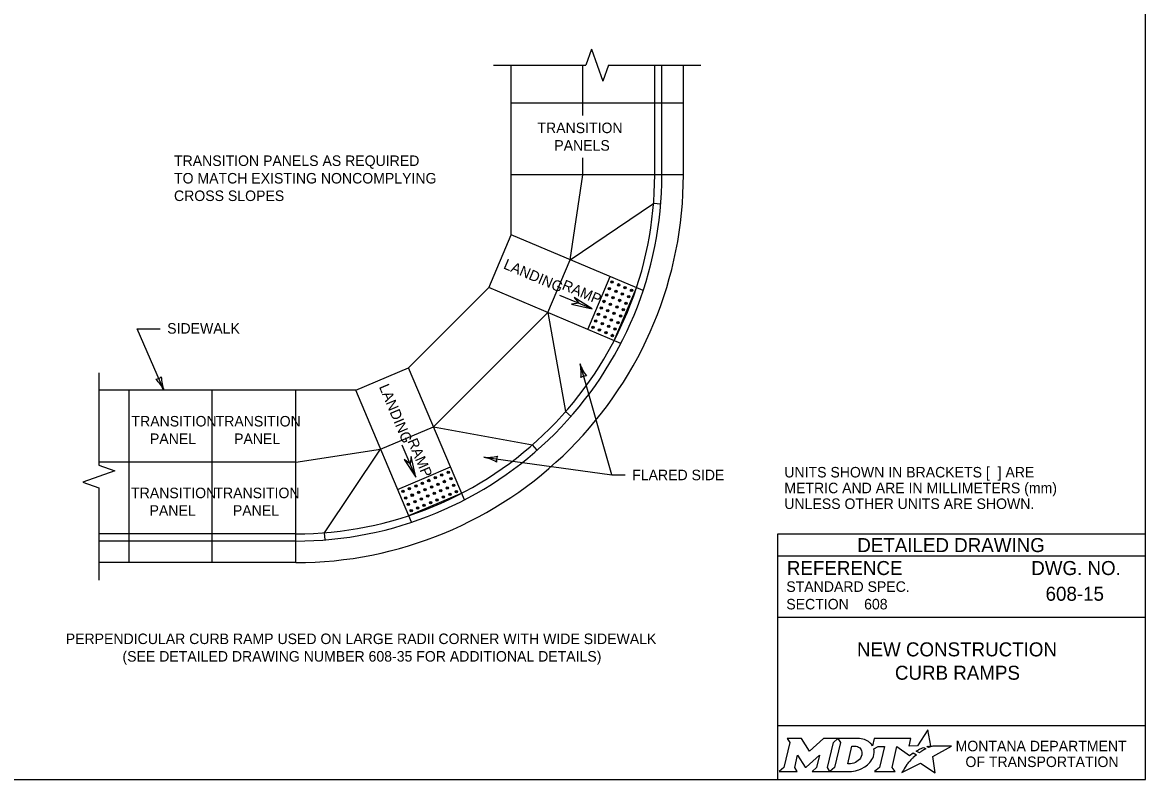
# Model space of a CAD drawing. Extents: x 49991.4 to 50021, y 49987.6 to 50011.4.
# Drawn here: x 50014.53 to 50020.94, y 49999.89 to 50004.2 of the extents above; entities that cross this region are included whole.
import ezdxf

# ---------------------------------------------------------------- set-up
doc = ezdxf.new("R2010")
doc.units = 0
for name, color, linetype in [('Default', 7, 'Continuous'), ('Level 1', 7, 'Continuous'), ('Level 2', 7, 'Continuous'), ('Level 3', 7, 'Continuous'), ('Level 4', 7, 'Continuous'), ('Level 6', 7, 'Continuous')]:
    doc.layers.add(name, color=color, linetype=linetype)

msp = doc.modelspace()

# ---------------------------------------------------------------- linework, layer by layer
at = {"layer": 'Default'}
for points in [[(50019.7003, 50000.0679), (50019.69, 50000.0735), (50019.7016, 50000.0763), (50019.7132, 50000.0783), (50019.6958, 50000.1684), (50019.6363, 50000.0771), (50019.589, 50000.0764), (50019.5993, 50000.1205), (50019.3901, 50000.1206), (50019.38, 50000.0781), (50019.3742, 50000.0864)], [(50019.7003, 50000.0679), (50019.69, 50000.0735), (50019.7016, 50000.0763), (50019.7132, 50000.0783), (50019.6958, 50000.1684), (50019.6363, 50000.0771), (50019.589, 50000.0764), (50019.5993, 50000.1205), (50019.3901, 50000.1206), (50019.38, 50000.0781), (50019.3742, 50000.0864)], [(50018.8933, 50000.1206), (50018.9074, 50000.0972), (50018.8739, 49999.9539), (50018.8482, 49999.9314), (50018.9498, 49999.9314), (50018.9363, 49999.9542), (50018.9525, 50000.0243), (50018.9962, 49999.9553), (50019.0015, 49999.9553), (50019.0766, 50000.0248), (50019.0602, 49999.9537), (50019.0355, 49999.9317), (50019.1371, 49999.9317), (50019.1233, 49999.955), (50019.1565, 50000.0974)], [(50018.8933, 50000.1206), (50018.9074, 50000.0972), (50018.8739, 49999.9539), (50018.8482, 49999.9314), (50018.9498, 49999.9314), (50018.9363, 49999.9542), (50018.9525, 50000.0243), (50018.9962, 49999.9553), (50019.0015, 49999.9553), (50019.0766, 50000.0248), (50019.0602, 49999.9537), (50019.0355, 49999.9317), (50019.1371, 49999.9317), (50019.1233, 49999.955), (50019.1565, 50000.0974)], [(50019.1565, 50000.0974), (50019.1818, 50000.1206), (50019.0994, 50000.1206), (50019.0198, 50000.0476), (50018.9753, 50000.1203), (50018.8933, 50000.1206)], [(50019.1565, 50000.0974), (50019.1818, 50000.1206), (50019.0994, 50000.1206), (50019.0198, 50000.0476), (50018.9753, 50000.1203), (50018.8933, 50000.1206)], [(50019.2954, 50000.1206), (50019.1818, 50000.1206), (50019.1965, 50000.0977), (50019.1626, 49999.9539), (50019.1371, 49999.9317), (50019.2477, 49999.9317)], [(50019.2954, 50000.1206), (50019.1818, 50000.1206), (50019.1965, 50000.0977), (50019.1626, 49999.9539), (50019.1371, 49999.9317), (50019.2477, 49999.9317)], [(50019.3194, 50000.0339), (50019.3182, 50000.0258), (50019.315, 50000.0165), (50019.3108, 50000.0083), (50019.3052, 50000.0008), (50019.2987, 49999.9939), (50019.2908, 49999.9876), (50019.2825, 49999.9829), (50019.2734, 49999.979), (50019.2643, 49999.9767), (50019.2551, 49999.9758), (50019.2392, 49999.9758), (50019.2628, 50000.0758), (50019.2788, 50000.0758), (50019.2864, 50000.0752), (50019.294, 50000.0733), (50019.3006, 50000.0703), (50019.3067, 50000.0661), (50019.3115, 50000.0611), (50019.3152, 50000.0551), (50019.3179, 50000.0489), (50019.3195, 50000.0415), (50019.3195, 50000.0385), (50019.3194, 50000.0339)], [(50019.3194, 50000.0339), (50019.3182, 50000.0258), (50019.315, 50000.0165), (50019.3108, 50000.0083), (50019.3052, 50000.0008), (50019.2987, 49999.9939), (50019.2908, 49999.9876), (50019.2825, 49999.9829), (50019.2734, 49999.979), (50019.2643, 49999.9767), (50019.2551, 49999.9758), (50019.2392, 49999.9758), (50019.2628, 50000.0758), (50019.2788, 50000.0758), (50019.2864, 50000.0752), (50019.294, 50000.0733), (50019.3006, 50000.0703), (50019.3067, 50000.0661), (50019.3115, 50000.0611), (50019.3152, 50000.0551), (50019.3179, 50000.0489), (50019.3195, 50000.0415), (50019.3195, 50000.0385), (50019.3194, 50000.0339)], [(50019.3868, 50000.0615), (50019.4114, 50000.0746), (50019.4483, 50000.0746), (50019.4197, 49999.9541), (50019.3922, 49999.9314), (50019.5084, 49999.9314), (50019.4914, 49999.9543), (50019.5196, 50000.0745), (50019.5909, 50000.0228), (50019.612, 50000.0379), (50019.6317, 50000.027)], [(50019.3868, 50000.0615), (50019.4114, 50000.0746), (50019.4483, 50000.0746), (50019.4197, 49999.9541), (50019.3922, 49999.9314), (50019.5084, 49999.9314), (50019.4914, 49999.9543), (50019.5196, 50000.0745), (50019.5909, 50000.0228), (50019.612, 50000.0379), (50019.6317, 50000.027)], [(50019.5759, 49999.9711), (50019.5606, 49999.9467), (50019.5559, 49999.9392), (50019.5501, 49999.9306), (50019.5478, 49999.9263), (50019.6531, 49999.9794), (50019.737, 49999.9243), (50019.7239, 50000.017), (50019.8308, 50000.0754), (50019.7815, 50000.0762), (50019.7514, 50000.0766), (50019.7306, 50000.0769), (50019.7238, 50000.0754), (50019.7189, 50000.0742), (50019.7105, 50000.0719), (50019.7003, 50000.0679)], [(50019.5759, 49999.9711), (50019.5606, 49999.9467), (50019.5559, 49999.9392), (50019.5501, 49999.9306), (50019.5478, 49999.9263), (50019.6531, 49999.9794), (50019.737, 49999.9243), (50019.7239, 50000.017), (50019.8308, 50000.0754), (50019.7815, 50000.0762), (50019.7514, 50000.0766), (50019.7306, 50000.0769), (50019.7238, 50000.0754), (50019.7189, 50000.0742), (50019.7105, 50000.0719), (50019.7003, 50000.0679)], [(50019.6499, 50000.0403), (50019.6475, 50000.0386), (50019.6292, 50000.0482), (50019.6395, 50000.0539), (50019.6436, 50000.0561), (50019.6522, 50000.0601), (50019.6579, 50000.0627), (50019.6658, 50000.0657), (50019.6731, 50000.0684), (50019.6849, 50000.061), (50019.6809, 50000.0589), (50019.6763, 50000.0564), (50019.6721, 50000.0542), (50019.6671, 50000.0513), (50019.6652, 50000.0502), (50019.6625, 50000.0486), (50019.66, 50000.0472), (50019.6577, 50000.0456), (50019.6551, 50000.0438), (50019.6524, 50000.042), (50019.6499, 50000.0403)], [(50019.6499, 50000.0403), (50019.6475, 50000.0386), (50019.6292, 50000.0482), (50019.6395, 50000.0539), (50019.6436, 50000.0561), (50019.6522, 50000.0601), (50019.6579, 50000.0627), (50019.6658, 50000.0657), (50019.6731, 50000.0684), (50019.6849, 50000.061), (50019.6809, 50000.0589), (50019.6763, 50000.0564), (50019.6721, 50000.0542), (50019.6671, 50000.0513), (50019.6652, 50000.0502), (50019.6625, 50000.0486), (50019.66, 50000.0472), (50019.6577, 50000.0456), (50019.6551, 50000.0438), (50019.6524, 50000.042), (50019.6499, 50000.0403)], [(50019.2934, 49999.939), (50019.3018, 49999.9416), (50019.3148, 49999.947), (50019.3352, 49999.958)], [(50019.2934, 49999.939), (50019.3018, 49999.9416), (50019.3148, 49999.947), (50019.3352, 49999.958)], [(50019.5898, 49999.9872), (50019.5898, 49999.9872)], [(50019.5898, 49999.9872), (50019.5898, 49999.9872)]]:
    msp.add_lwpolyline(points, dxfattribs=at)
for centre, radius, start, end in [((50019.2745, 50000.0595), 0.1183, 300.91025, 339.13831), ((50019.2745, 50000.0595), 0.1183, 300.91025, 339.13831), ((50019.3185, 50000.0422), 0.0709, 339.53292, 15.85821), ((50019.3185, 50000.0422), 0.0709, 339.53292, 15.85821)]:
    msp.add_arc(centre, radius, start, end, dxfattribs=at)
for centre, major_axis, ratio, start_param, end_param in [((50019.2933, 50000.0732), (0.0834, -0.0037), 0.568097, 0.61298, 1.570796), ((50019.2933, 50000.0732), (0.0834, -0.0037), 0.568097, 0.61298, 1.570796), ((50019.3489, 50000.0805), (0.0361, -0.0295), 0.469099, 1.225588, 1.570796), ((50019.3489, 50000.0805), (0.0361, -0.0295), 0.469099, 1.225588, 1.570796), ((50019.6206, 50000.0173), (-0.0112, -0.0097), 0.021651, 3.157348, 6.283185), ((50019.6206, 50000.0173), (-0.0112, -0.0097), 0.021651, 3.157348, 6.283185), ((50019.5829, 49999.9791), (-0.00694, -0.00806), 0.008222, 0, 3.137361), ((50019.5829, 49999.9791), (-0.00694, -0.00806), 0.008222, 0, 3.137361), ((50019.5996, 49999.9974), (-0.0098, -0.0102), 0.016458, 3.141593, 6.279097), ((50019.5996, 49999.9974), (-0.0098, -0.0102), 0.016458, 3.141593, 6.279097), ((50019.248, 50000.08), (0, 0.1484), 0.987302, 3.139398, 3.456847), ((50019.248, 50000.08), (0, 0.1484), 0.987302, 3.139398, 3.456847)]:
    msp.add_ellipse(centre, major_axis=major_axis, ratio=ratio, start_param=start_param, end_param=end_param, dxfattribs=at)
at = {"layer": 'Level 1'}
for p, q in [((50017.3181, 50002.9934), (50017.3181, 50003.9613)), ((50017.7277, 50003.6732), (50017.7277, 50003.9613)), ((50018.1373, 50003.335), (50018.1373, 50003.9613)), ((50018.1783, 50003.3351), (50018.1783, 50003.9613)), ((50018.3012, 50003.3351), (50018.3012, 50003.9613)), ((50017.7277, 50003.7447), (50017.3181, 50003.7447)), ((50018.3012, 50003.7447), (50017.7277, 50003.7447)), ((50017.7277, 50003.3351), (50017.7277, 50003.4332)), ((50017.7277, 50003.3351), (50017.3181, 50003.3351)), ((50018.3012, 50003.3351), (50017.7277, 50003.3351)), ((50017.6545, 50002.8512), (50018.1308, 50003.1714)), ((50018.1716, 50003.1682), (50018.1308, 50003.1714)), ((50018.0712, 50002.675), (50017.3182, 50002.9934)), ((50017.7557, 50002.4528), (50017.8833, 50002.7545)), ((50017.1904, 50002.6917), (50016.7326, 50002.2338)), ((50017.9437, 50002.3733), (50017.1904, 50002.6917)), ((50017.9059, 50002.3893), (50018.0334, 50002.691)), ((50017.527, 50002.5494), (50017.629, 50001.9846)), ((50017.0512, 50001.4807), (50016.7326, 50002.2338)), ((50016.431, 50002.1063), (50014.9646, 50002.1063)), ((50015.1379, 50001.6967), (50015.1379, 50002.1063)), ((50015.6117, 50001.6967), (50015.6117, 50002.1063)), ((50016.0893, 50001.6967), (50016.0893, 50002.1063)), ((50016.7493, 50001.3531), (50016.431, 50002.1063)), ((50017.6599, 50001.9576), (50017.629, 50001.9846)), ((50016.8749, 50001.8974), (50017.4397, 50001.7954)), ((50016.2528, 50001.2936), (50016.5732, 50001.7698)), ((50017.4668, 50001.7646), (50017.4397, 50001.7954)), ((50016.0893, 50001.6967), (50014.9646, 50001.6967)), ((50015.1379, 50001.1232), (50015.1379, 50001.6967)), ((50015.6117, 50001.1232), (50015.6117, 50001.6967)), ((50016.0893, 50001.1232), (50016.0893, 50001.6967)), ((50016.8208, 50001.6049), (50016.9717, 50001.6687)), ((50016.6698, 50001.5411), (50016.8208, 50001.6049)), ((50016.7333, 50001.391), (50017.0352, 50001.5186)), ((50016.0893, 50001.287), (50014.9646, 50001.287)), ((50016.0893, 50001.2461), (50014.9646, 50001.2461)), ((50016.2562, 50001.2527), (50016.2528, 50001.2936)), ((50016.0893, 50001.1232), (50014.9646, 50001.1232))]:
    msp.add_line(p, q, dxfattribs=at)
msp.add_lwpolyline([(50020.9378, 50008.1646), (50009.7374, 50008.1646), (50009.7374, 49999.8856), (50020.9378, 49999.8856)], close=True, dxfattribs=at)
msp.add_lwpolyline([(50020.9378, 50008.1646), (50009.7374, 50008.1646), (50009.7374, 49999.8856), (50020.9378, 49999.8856)], close=True, dxfattribs=at)
for points in [[(50016.0893, 50001.6967), (50016.5732, 50001.7698), (50016.8749, 50001.8974), (50017.527, 50002.5494), (50017.6545, 50002.8512), (50017.7277, 50003.3351)], [(50017.1906, 50002.6916), (50017.3182, 50002.9934)], [(50016.431, 50002.1063), (50016.7326, 50002.2338)]]:
    msp.add_lwpolyline(points, dxfattribs=at)
for centre, radius in [((50017.8942, 50002.7234), 0.00675), ((50017.8942, 50002.7234), 0.00375), ((50017.9311, 50002.7078), 0.00675), ((50017.9311, 50002.7078), 0.00375), ((50017.8631, 50002.6497), 0.00675), ((50017.8631, 50002.6497), 0.00375), ((50017.8786, 50002.6865), 0.00675), ((50017.8786, 50002.6865), 0.00375), ((50017.9155, 50002.671), 0.00675), ((50017.9155, 50002.671), 0.00375), ((50017.9523, 50002.6554), 0.00675), ((50017.9523, 50002.6554), 0.00375), ((50017.9679, 50002.6922), 0.00675), ((50017.9679, 50002.6922), 0.00375), ((50017.9892, 50002.6398), 0.00675), ((50018.0048, 50002.6767), 0.00675), ((50018.0048, 50002.6767), 0.00375), ((50017.8319, 50002.576), 0.00675), ((50017.8475, 50002.6128), 0.00675), ((50017.8475, 50002.6128), 0.00375), ((50017.8844, 50002.5973), 0.00675), ((50017.8844, 50002.5973), 0.00375), ((50017.8999, 50002.6341), 0.00675), ((50017.8999, 50002.6341), 0.00375), ((50017.9212, 50002.5817), 0.00675), ((50017.9212, 50002.5817), 0.00375), ((50017.9368, 50002.6185), 0.00675), ((50017.9368, 50002.6185), 0.00375), ((50017.9736, 50002.603), 0.00675), ((50017.9736, 50002.603), 0.00375), ((50017.9892, 50002.6398), 0.00375), ((50017.8164, 50002.5391), 0.00675), ((50017.8164, 50002.5391), 0.00375), ((50017.8319, 50002.576), 0.00375), ((50017.8532, 50002.5236), 0.00675), ((50017.8532, 50002.5236), 0.00375), ((50017.8688, 50002.5604), 0.00675), ((50017.8688, 50002.5604), 0.00375), ((50017.9056, 50002.5448), 0.00675), ((50017.9056, 50002.5448), 0.00375), ((50017.9425, 50002.5293), 0.00675), ((50017.9425, 50002.5293), 0.00375), ((50017.958, 50002.5661), 0.00675), ((50017.958, 50002.5661), 0.00375), ((50017.7852, 50002.4655), 0.00675), ((50017.7852, 50002.4655), 0.00375), ((50017.8008, 50002.5023), 0.00675), ((50017.8008, 50002.5023), 0.00375), ((50017.8221, 50002.4499), 0.00675), ((50017.8221, 50002.4499), 0.00375), ((50017.8376, 50002.4867), 0.00675), ((50017.8376, 50002.4867), 0.00375), ((50017.8745, 50002.4712), 0.00675), ((50017.8745, 50002.4712), 0.00375), ((50017.8901, 50002.508), 0.00675), ((50017.8901, 50002.508), 0.00375), ((50017.9113, 50002.4556), 0.00675), ((50017.9113, 50002.4556), 0.00375), ((50017.9269, 50002.4924), 0.00675), ((50017.9269, 50002.4924), 0.00375), ((50017.8589, 50002.4343), 0.00675), ((50017.8589, 50002.4343), 0.00375), ((50017.8958, 50002.4187), 0.00675), ((50017.8958, 50002.4187), 0.00375), ((50016.9219, 50001.6227), 0.00675), ((50016.9219, 50001.6227), 0.00375), ((50016.9588, 50001.6383), 0.00675), ((50016.9588, 50001.6383), 0.00375), ((50016.7746, 50001.5604), 0.00675), ((50016.7746, 50001.5604), 0.00375), ((50016.8114, 50001.5759), 0.00675), ((50016.8114, 50001.5759), 0.00375), ((50016.8483, 50001.5915), 0.00675), ((50016.8483, 50001.5915), 0.00375), ((50016.8638, 50001.5547), 0.00675), ((50016.8638, 50001.5547), 0.00375), ((50016.8851, 50001.6071), 0.00675), ((50016.8851, 50001.6071), 0.00375), ((50016.9007, 50001.5703), 0.00675), ((50016.9007, 50001.5703), 0.00375), ((50016.9375, 50001.5858), 0.00675), ((50016.9375, 50001.5858), 0.00375), ((50016.9531, 50001.549), 0.00675), ((50016.9744, 50001.6014), 0.00675), ((50016.9744, 50001.6014), 0.00375), ((50016.9899, 50001.5646), 0.00675), ((50016.9899, 50001.5646), 0.00375), ((50016.7009, 50001.5292), 0.00675), ((50016.7009, 50001.5292), 0.00375), ((50016.7165, 50001.4924), 0.00675), ((50016.7165, 50001.4924), 0.00375), ((50016.7377, 50001.5448), 0.00675), ((50016.7377, 50001.5448), 0.00375), ((50016.7533, 50001.5079), 0.00675), ((50016.7533, 50001.5079), 0.00375), ((50016.7901, 50001.5235), 0.00675), ((50016.7901, 50001.5235), 0.00375), ((50016.8057, 50001.4867), 0.00675), ((50016.827, 50001.5391), 0.00675), ((50016.827, 50001.5391), 0.00375), ((50016.8426, 50001.5023), 0.00675), ((50016.8426, 50001.5023), 0.00375), ((50016.8794, 50001.5178), 0.00675), ((50016.8794, 50001.5178), 0.00375), ((50016.9162, 50001.5334), 0.00675), ((50016.9162, 50001.5334), 0.00375), ((50016.9318, 50001.4966), 0.00675), ((50016.9318, 50001.4966), 0.00375), ((50016.9531, 50001.549), 0.00375), ((50016.9687, 50001.5122), 0.00675), ((50016.9687, 50001.5122), 0.00375), ((50017.0055, 50001.5277), 0.00675), ((50017.0055, 50001.5277), 0.00375), ((50016.732, 50001.4555), 0.00675), ((50016.732, 50001.4555), 0.00375), ((50016.7689, 50001.4711), 0.00675), ((50016.7689, 50001.4711), 0.00375), ((50016.7845, 50001.4343), 0.00675), ((50016.7845, 50001.4343), 0.00375), ((50016.8057, 50001.4867), 0.00375), ((50016.8213, 50001.4498), 0.00675), ((50016.8213, 50001.4498), 0.00375), ((50016.8581, 50001.4654), 0.00675), ((50016.8581, 50001.4654), 0.00375), ((50016.895, 50001.481), 0.00675), ((50016.895, 50001.481), 0.00375), ((50016.7476, 50001.4187), 0.00675), ((50016.7476, 50001.4187), 0.00375)]:
    msp.add_circle(centre, radius, dxfattribs=at)
for radius, start, end in [(2.2118, 269.99767, 0.00191), (2.048, 269.99748, 0.00206), (2.089, 269.99753, 0.00202)]:
    msp.add_arc((50016.0893, 50003.3351), radius, start, end, dxfattribs=at)
at = {"layer": 'Level 3'}
for p, q in [((50017.7799, 50002.5702), (50017.5967, 50002.6472)), ((50015.337, 50002.1063), (50015.1837, 50002.4564)), ((50015.1837, 50002.4564), (50015.3154, 50002.4564)), ((50017.8918, 50001.6231), (50017.7111, 50002.2565)), ((50016.7736, 50001.6102), (50016.6963, 50001.7931)), ((50017.1619, 50001.7239), (50017.8918, 50001.6231)), ((50017.8918, 50001.6231), (50017.9686, 50001.6231))]:
    msp.add_line(p, q, dxfattribs=at)
for points in [[(50017.662, 50002.5972), (50017.7799, 50002.5702), (50017.6783, 50002.636), (50017.7036, 50002.6024)], [(50016.7081, 50001.7118), (50016.7736, 50001.6102), (50016.7468, 50001.7282), (50016.7415, 50001.6865)]]:
    msp.add_lwpolyline(points, close=True, dxfattribs=at)
for centre, radius, start, end in [((50017.495, 50002.2044), 0.2223, 353.37871, 13.56221), ((50017.9318, 50002.3314), 0.233, 198.75001, 217.99986), ((50015.2856, 50002.2237), 0.0548, 275.78611, 311.50847), ((50015.1285, 50002.0024), 0.233, 26.4746, 45.72445), ((50015.5442, 50002.187), 0.2223, 181.1033, 201.28681), ((50017.7463, 50002.1332), 0.0548, 88.06151, 123.78388), ((50017.1824, 50001.956), 0.233, 264.96444, 284.21429), ((50017.1225, 50001.5051), 0.2223, 59.59314, 79.77664), ((50017.2889, 50001.7064), 0.0548, 154.27594, 189.99831)]:
    msp.add_arc(centre, radius, start, end, dxfattribs=at)
at = {"layer": 'Level 4'}
for p, q in [((50020.9378, 50001.2856), (50018.8378, 50001.2856)), ((50018.8378, 50001.2856), (50018.8378, 49999.8856)), ((50020.9378, 50001.1606), (50018.8378, 50001.1606)), ((50020.9378, 50000.8106), (50018.8378, 50000.8106)), ((50020.9378, 50000.1925), (50018.8378, 50000.1925))]:
    msp.add_line(p, q, dxfattribs=at)
at = {"layer": 'Level 6'}
for p, q in [((50017.7772, 50004.0527), (50017.7448, 50003.9613)), ((50017.7772, 50004.0527), (50017.8096, 50003.9613)), ((50017.2181, 50003.9613), (50017.7448, 50003.9613)), ((50017.8096, 50003.9613), (50017.842, 50003.8699)), ((50017.8744, 50003.9613), (50017.842, 50003.8699)), ((50017.8744, 50003.9613), (50018.4012, 50003.9613)), ((50014.9646, 50002.2063), (50014.9646, 50001.6795)), ((50014.9646, 50001.6795), (50015.056, 50001.6471)), ((50015.056, 50001.6471), (50014.9646, 50001.6147)), ((50014.9646, 50001.6147), (50014.8732, 50001.5823)), ((50014.8732, 50001.5823), (50014.9646, 50001.5499)), ((50014.9646, 50001.5499), (50014.9646, 50001.0232))]:
    msp.add_line(p, q, dxfattribs=at)

# ---------------------------------------------------------------- texts
at = {"layer": 'Default'}
for s, p in [('MONTANA DEPARTMENT', (50019.854, 50000.0468)), ('MONTANA DEPARTMENT', (50019.854, 50000.0468)), ('OF TRANSPORTATION', (50019.9102, 49999.9568)), ('OF TRANSPORTATION', (50019.9102, 49999.9568))]:
    msp.add_text(s, height=0.06, rotation=360, dxfattribs=at).set_placement(p)
at = {"layer": 'Level 2'}
for s, height, p in [('TRANSITION', 0.06, (50017.4681, 50003.5732)), ('PANELS ', 0.06, (50017.5643, 50003.4732)), ('TRANSITION PANELS AS REQUIRED', 0.06, (50015.3943, 50003.3859)), ('TO MATCH EXISTING NONCOMPLYING', 0.06, (50015.3943, 50003.2859)), ('CROSS SLOPES', 0.06, (50015.3943, 50003.1859)), ('SIDEWALK', 0.06, (50015.3554, 50002.4294)), ('TRANSITION', 0.06, (50015.1517, 50001.8997)), ('TRANSITION', 0.06, (50015.6317, 50001.8997)), ('PANEL ', 0.06, (50015.2571, 50001.7997)), ('PANEL ', 0.06, (50015.7371, 50001.7997)), ('FLARED SIDE', 0.06, (50018.0086, 50001.5931)), ('UNITS SHOWN IN BRACKETS [  ] ARE ', 0.06, (50018.8768, 50001.6089)), ('METRIC AND ARE IN MILLIMETERS (mm) ', 0.06, (50018.8768, 50001.5189)), ('TRANSITION', 0.06, (50015.1494, 50001.4907)), ('TRANSITION', 0.06, (50015.6248, 50001.4907)), ('PANEL ', 0.06, (50015.2548, 50001.3907)), ('PANEL ', 0.06, (50015.7303, 50001.3907)), ('UNLESS OTHER UNITS ARE SHOWN.', 0.06, (50018.8768, 50001.4289)), ('608-15', 0.08, (50020.3675, 50000.9055)), ('608', 0.06, (50019.332, 50000.8561)), ('PERPENDICULAR CURB RAMP USED ON LARGE RADII CORNER WITH WIDE SIDEWALK', 0.06, (50014.7765, 50000.6584)), ('NEW CONSTRUCTION', 0.08, (50019.2913, 50000.5882)), ('(SEE DETAILED DRAWING NUMBER 608-35 FOR ADDITIONAL DETAILS) ', 0.06, (50015.1002, 50000.5584)), ('CURB RAMPS', 0.08, (50019.5079, 50000.4548))]:
    msp.add_text(s, height=height, dxfattribs=at).set_placement(p)
for s, rotation, p in [('LANDING', 337.01134, (50017.2695, 50002.8027)), ('RAMP', 337.1968, (50017.603, 50002.6839)), ('LANDING', 292.82914, (50016.5627, 50002.1267)), ('RAMP', 292.91015, (50016.7251, 50001.8169))]:
    msp.add_text(s, height=0.06, rotation=rotation, dxfattribs=at).set_placement(p)
at = {"layer": 'Level 4'}
for s, height, p in [('DETAILED DRAWING', 0.08, (50019.2931, 50001.1831)), ('REFERENCE', 0.08, (50018.8914, 50001.0522)), ('DWG. NO.', 0.08, (50020.2856, 50001.0522)), ('STANDARD SPEC.', 0.06, (50018.8881, 50000.9562)), ('SECTION', 0.06, (50018.8881, 50000.8562))]:
    msp.add_text(s, height=height, dxfattribs=at).set_placement(p)

doc.saveas('drawing.dxf')
